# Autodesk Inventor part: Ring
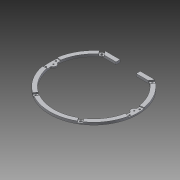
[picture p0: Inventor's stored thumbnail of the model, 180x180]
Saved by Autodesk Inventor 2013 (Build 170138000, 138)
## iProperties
Created: 2012-09
Part Number: Ring
Material: Aluminium 6061
Document SubType Name: Modeling
Designer: rYan
Mass: 46.9526 g
Surface Area: 125.551 cm^2
Volume: 17.3257 cm^3
Density: 2.71 g/cm^3
d0: 174,000 mm
d1: 158,000 mm
d4: 5,000 mm
d5: 0,00 grd
d21: 50,000 mm
d22: 66,000 mm
d23: 70,000 mm
d24: 44,000 mm
d25: 4,200 mm
d41: 8,000 mm
d42: 72,000 mm
d44: 79,000 mm
d45: 87,000 mm
d46: 8,000 mm
d48: 8,000 mm
d49: 3,000 mm
d50: 0,00 grd
d51: 2,000 mm
Author: rYan
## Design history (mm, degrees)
sketch "Skizze1"
  geometry: L1 (0, 107.409)-(0, -140.453) reference; L2 (-129.1, 0)-(21.517, 0) reference; L3 (0, -79)-(0, -87); L4 (-48.836, 72)-(0, 72); L5 (0, 72)-(0, 64); L6 (0, 64)-(-46.314, 64); A1 r 87 centre (0, 0) between (-48.836, 72) and (0, -87); A2 r 79 centre (0, 0) between (-46.314, 64) and (0, -79); A3 r 6 centre (-80, 0) between (-78.781, -5.875) and (-78.781, 5.875); 1 further point
  constraints: 8 end point, 8 point on circle, 3 centre point, 2 coincident, 2 collinear, 2 parallel, 1 perpendicular, 1 point on line
  dimensions: "d41" = 8 distance of L4.end L5.end; "d42" = 72 distance between parallel lines of L2 L4; "d44" = 79 radius of A2; "d45" = 87 radius of A1; "d149" = 12 diameter of A3; "d150" = 80 distance from line of L1 A3.centre
extrude "Extrusion1" new body sketch "Skizze1" distance "d4" = 5; taper "d5" = 0 deg
sketch "Skizze5"
  geometry: L1 (0, 103.8)-(0, -118.8) reference; L2 (-104.4, 0)-(17.4, 0) reference; 3 further points
  dimensions: "d21" = 50 distance from line of point (-50, 66) L1; "d22" = 66 distance from line of point (-50, 66) L2; "d23" = 70 distance from line of L2 point (-44, -70); "d24" = 44 distance from line of L1 point (-44, -70)
hole "Bohrung2" sketch "Skizze5" at (-50, 66), (-44, -70) diameter "d25" = 4.2; stored, may be unused: countersink angle "d29" = 90 deg, drill point angle "d31" = 118 deg; dims "d26" = 6, "d27" = 7.5, "d28" = 3, "d30" = 8
sketch "Skizze7"
  geometry: L1 (0, 0)-(-50, 66); L2 (0, 0)-(-44, -70); L3 (-43.467, 64)-(-49.843, 59.169); L4 (-49.843, 59.169)-(-55.724, 66.932); L5 (-55.724, 66.932)-(-49.347, 71.762); L6 (-49.347, 71.762)-(-43.467, 64); L7 (-45.374, -64.67)-(-38.601, -68.927); L8 (-38.601, -68.927)-(-42.912, -75.786); L9 (-42.912, -75.786)-(-49.685, -71.529); L10 (-49.685, -71.529)-(-45.374, -64.67); L11 (-46.314, 64)-(0, 64) reference; C1 r 2.1 at (-44, -70) reference; C2 r 2.1 at (-50, 66) reference; A1 r 87 centre (0, 0) between (-48.836, 72) and (0, -87) reference; A2 r 79 centre (0, 0) between (-46.314, 64) and (0, -79) reference
  constraints: 20 end point, 5 perpendicular, 3 parallel, 2 coincident, 2 tangent, 1 point on circle, 1 point on line, 2 other
  dimensions: "d46" = 8 distance of L3.start L3.end; "d48" = 8 distance of L7.start L7.end (= d46)
extrude "Extrusion4" cut sketch "Skizze7" distance "d49" = 3; taper "d50" = 0 deg
fillet "Rundung1" dims "d51" = 2
sketch "Skizze13"
  geometry: L1 (-120, 0)-(20, 0) reference; L2 (0, 103.8)-(0, -118.8) reference; L3 (0, 0)-(-100, 15.838); L4 (-100, 15.838)-(-100, -19.438); L5 (-100, -19.438)-(0, 0); A1 r 87 centre (0, 0) between (-55.668, 66.858) and (-49.637, -71.451) reference
  constraints: 6 end point, 1 perpendicular
  dimensions: "d94" = 100 distance between parallel lines of L2 L4; "d95" = 9 deg angle of L1 L3; "d96" = 20 deg angle of L5 L3
extrude "Extrusion8" cut sketch "Skizze13" distance "d97" = 2; taper "d98" = 0 deg
sketch "Skizze14"
  geometry: L1 (-104.4, 0)-(17.4, 0) reference; L2 (0, 103.8)-(0, -118.8) reference; L3 (-83, 27.142)-(-83, -22.209); 2 further points
  constraints: 2 end point, 2 point on line, 1 parallel
  dimensions: "d99" = 83 distance between parallel lines of L2 L3; "d100" = 8 distance from line of L1 point (-83, 8); "d101" = 20 distance of point (-83, -12) point (-83, 8)
hole "Bohrung6" sketch "Skizze14" at (-83, 8), (-83, -12) diameter "d102" = 3.2; stored, may be unused: countersink angle "d106" = 90 deg, drill point angle "d108" = 118 deg; dims "d103" = 6, "d104" = 4, "d105" = 2, "d107" = 8
mirror "Spiegeln1"
sketch "Skizze17"
  geometry: L1 (45.662, 64)-(-45.662, 64) reference; L2 (-20, 78)-(20, 78); L3 (20, 78)-(20, 58); L4 (20, 58)-(-20, 58); L5 (-20, 58)-(-20, 78); L6 (0, -120)-(0, 111) reference
  constraints: 8 end point, 2 parallel, 1 horizontal, 1 perpendicular, 1 other
  dimensions: "d138" = 20 distance of L4.end L2.start; "d140" = 40 distance of L3.end L4.end; "d141" = 6 distance between parallel lines of L1 L4
extrude "Extrusion9" cut sketch "Skizze17" stored distance "d142" = 1; taper "d143" = 0 deg
sketch "Skizze20"
  geometry: A1 r 6 centre (-80, 0) between (-78.781, -5.875) and (-78.781, 5.875) reference; A2 r 6 centre (80, 0) between (78.781, 5.875) and (78.781, -5.875) reference; 1 further point
hole "Bohrung10" sketch "Skizze20" at (-80, 0), (80, 0) diameter "d158" = 2.459; stored, may be unused: countersink angle "d162" = 90 deg, drill point angle "d164" = 118 deg; dims "d159" = 6, "d160" = 4, "d161" = 2, "d163" = 8
fillet "Rundung2" dims "d165" = 2
node "Volumenkörper1"
other parameters: "d0" = 174, "d1" = 158
